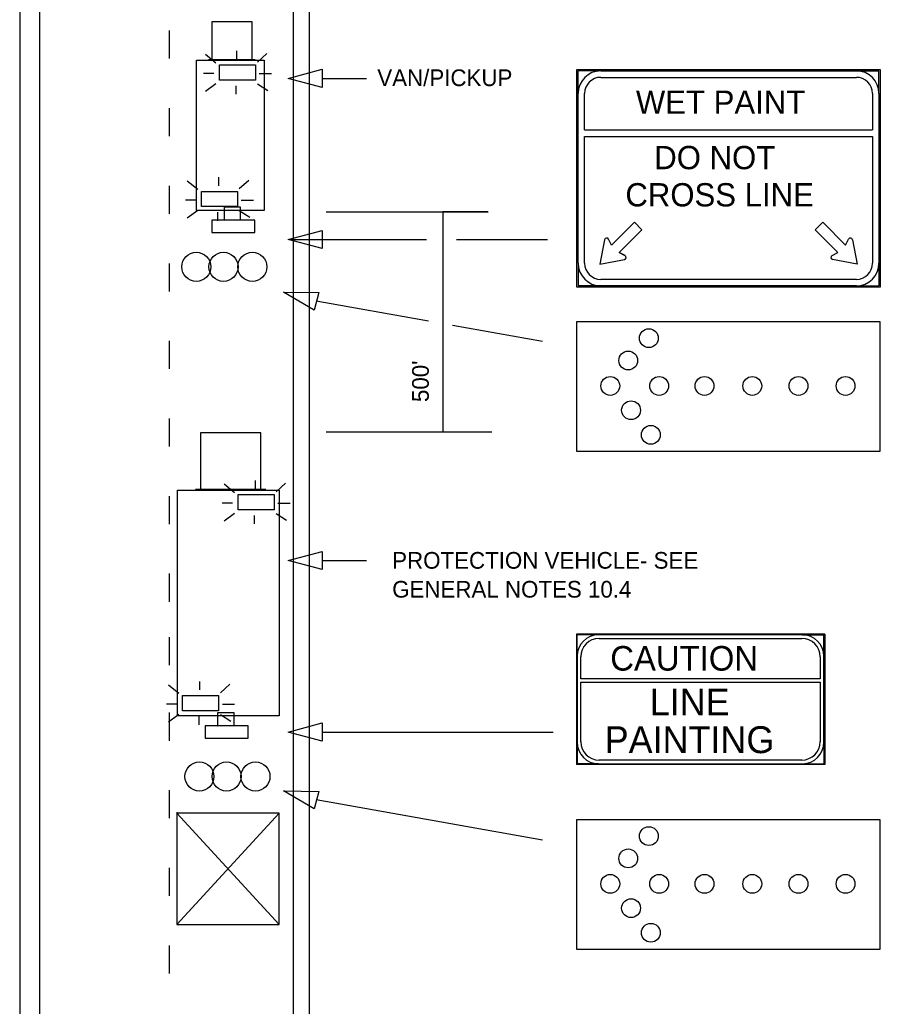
# Model space of a CAD drawing. Extents: x 1531.71 to 1538.58, y 1529.59 to 1539.48.
# Drawn here: x 1535.052 to 1538.149, y 1533.331 to 1536.879 of the extents above; entities that cross this region are included whole.
import ezdxf

# ---------------------------------------------------------------- set-up
doc = ezdxf.new("R2010")
doc.units = 0
for name, color, linetype in [('DETL-DIMS', 7, 'Continuous'), ('DETL-LINE', 7, 'Continuous'), ('DETL-NOTE', 7, 'Continuous'), ('USER-BORD', 7, 'Continuous')]:
    doc.layers.add(name, color=color, linetype=linetype)

# ---------------------------------------------------------------- blocks, each defined once
blk = doc.blocks.new('AP1')
at = {"layer": 'USER-BORD'}
for p, q in [((-0.0005, -0.0035), (-0.0005, -0.5033)), ((1.1745, -0.0035), (-0.0005, -0.0035)), ((0.1953, -0.0035), (0.1953, -0.0035)), ((0.3911, -0.0035), (0.3911, -0.0035)), ((0.587, -0.0035), (0.587, -0.0035)), ((0.7828, -0.0035), (0.7828, -0.0035)), ((0.9787, -0.0035), (0.9787, -0.0035)), ((1.1745, -0.5033), (1.1745, -0.0035)), ((-0.0005, -0.5033), (1.1745, -0.5033))]:
    blk.add_line(p, q, dxfattribs=at)
for centre in [(0.2793, -0.0665), (0.1995, -0.1528), (0.13, -0.2513), (0.3192, -0.2513), (0.4945, -0.2513), (0.6795, -0.2513), (0.858, -0.2513), (1.0402, -0.2513), (0.2103, -0.3452), (0.2869, -0.4403)]:
    blk.add_circle(centre, 0.0364, dxfattribs=at)
blk = doc.blocks.new('BAR')
at = {"layer": 'USER-BORD'}
for p, q in [((0.0695, 0.1172), (0.0695, 0.0842)), ((-0.011, 0.0696), (-0.0512, 0.1025)), ((0.15, 0.0732), (0.1866, 0.1062)), ((0.0037, 0.0037), (0.0037, 0.0622)), ((0.0037, 0.0622), (0.1427, 0.0622)), ((0.1427, 0.0622), (0.1427, 0.0037)), ((-0.0183, 0.0293), (-0.0585, 0.0293)), ((0.1427, 0.0037), (0.0037, 0.0037)), ((0.1573, 0.0293), (0.2049, 0.0293)), ((-0.011, -0.011), (-0.0512, -0.0403)), ((0.0658, -0.0183), (0.0658, -0.0513)), ((0.15, -0.011), (0.1902, -0.0366))]:
    blk.add_line(p, q, dxfattribs=at)
blk = doc.blocks.new('SIGN13')
at = {"layer": 'USER-BORD'}
for points in [[(-0.0134, 0.0182), (0.011, 0.0189), (0.011, 0.0371), (-0.0134, 0.0371)], [(-0.0314, 0.0182), (-0.0314, 0), (0.032, 0), (0.032, 0.0182)]]:
    blk.add_lwpolyline(points, close=True, dxfattribs=at)

msp = doc.modelspace()

# ---------------------------------------------------------------- linework, layer by layer
at = {"layer": 'DETL-DIMS'}
for p, q in [((1536.1408, 1536.6681), (1536.2998, 1536.6681)), ((1536.1554, 1536.1884), (1536.7372, 1536.1884)), ((1536.5747, 1536.1884), (1536.5747, 1535.3949)), ((1536.7372, 1536.1884), (1536.5747, 1536.1884)), ((1536.028, 1536.0882), (1536.3863, 1536.0882)), ((1536.3863, 1536.0882), (1536.5157, 1536.0882)), ((1536.6236, 1536.0882), (1536.951, 1536.0882)), ((1536.1184, 1535.8679), (1536.5226, 1535.796)), ((1536.6097, 1535.7805), (1536.933, 1535.723)), ((1536.7508, 1535.3949), (1536.1554, 1535.3949)), ((1536.1408, 1534.9341), (1536.2998, 1534.9341)), ((1536.1408, 1534.317), (1536.9717, 1534.317)), ((1536.1184, 1534.0741), (1536.933, 1533.9291))]:
    msp.add_line(p, q, dxfattribs=at)
for points in [[(1536.018, 1536.6681), (1536.1408, 1536.7007), (1536.1408, 1536.6356)], [(1536.018, 1536.0882), (1536.1408, 1536.1207), (1536.1408, 1536.0557)], [(1536.0018, 1535.899), (1536.1289, 1535.8975), (1536.1115, 1535.8347)], [(1536.018, 1534.9341), (1536.1408, 1534.9666), (1536.1408, 1534.9015)], [(1536.018, 1534.317), (1536.1408, 1534.3495), (1536.1408, 1534.2845)], [(1536.0018, 1534.105), (1536.1289, 1534.1035), (1536.1115, 1534.0407)]]:
    msp.add_lwpolyline(points, close=True, dxfattribs=at)
at = {"layer": 'DETL-LINE'}
for p, q in [((1535.0522, 1538.4412), (1535.0522, 1531.4327)), ((1535.1234, 1538.4412), (1535.1234, 1531.4327)), ((1536.0366, 1538.4412), (1536.0366, 1531.4327)), ((1536.0938, 1538.4412), (1536.0938, 1531.4327)), ((1535.8883, 1536.8711), (1535.743, 1536.8711)), ((1535.743, 1536.8711), (1535.743, 1536.7356)), ((1535.8883, 1536.7356), (1535.8883, 1536.8711)), ((1535.5917, 1536.7389), (1535.5917, 1536.8398)), ((1535.6879, 1536.1928), (1535.6879, 1536.7335)), ((1535.6879, 1536.7335), (1535.932, 1536.7335)), ((1535.7316, 1536.7356), (1535.8996, 1536.7356)), ((1535.761, 1536.7335), (1535.875, 1536.7335)), ((1535.932, 1536.7335), (1535.932, 1536.1928)), ((1537.0567, 1536.6997), (1538.1485, 1536.6997)), ((1537.0567, 1535.9169), (1537.0567, 1536.6997)), ((1537.1427, 1536.6949), (1537.0615, 1536.6949)), ((1537.0615, 1536.6137), (1537.0615, 1536.6949)), ((1537.1427, 1536.6949), (1538.0625, 1536.6949)), ((1538.0625, 1536.6949), (1538.1437, 1536.6949)), ((1538.1437, 1536.6137), (1538.1437, 1536.6949)), ((1538.1485, 1536.6997), (1538.1485, 1535.9169)), ((1537.1427, 1536.6717), (1538.0625, 1536.6717)), ((1537.0615, 1536.0029), (1537.0615, 1536.6137)), ((1537.0847, 1536.4824), (1537.0847, 1536.6137)), ((1538.1205, 1536.6137), (1538.1205, 1536.4824)), ((1538.1437, 1536.6137), (1538.1437, 1536.0029)), ((1535.5917, 1536.4599), (1535.5917, 1536.5608)), ((1537.0847, 1536.4824), (1538.1205, 1536.4824)), ((1537.0847, 1536.0029), (1537.0847, 1536.4592)), ((1537.0847, 1536.4592), (1538.1205, 1536.4592)), ((1538.1205, 1536.4592), (1538.1205, 1536.0029)), ((1535.5917, 1536.1809), (1535.5917, 1536.2817)), ((1535.932, 1536.1928), (1535.6879, 1536.1928)), ((1537.264, 1536.151), (1537.1815, 1536.0686)), ((1537.2092, 1536.0413), (1537.2912, 1536.1234)), ((1537.2912, 1536.1234), (1537.264, 1536.151)), ((1537.914, 1536.1234), (1537.9416, 1536.151)), ((1537.9964, 1536.0413), (1537.914, 1536.1234)), ((1537.9416, 1536.151), (1538.0236, 1536.0686)), ((1537.1567, 1536.0878), (1537.1399, 1535.9997)), ((1537.1815, 1536.0686), (1537.1707, 1536.0898)), ((1538.0236, 1536.0686), (1538.0344, 1536.0898)), ((1538.0485, 1536.0878), (1538.0653, 1535.9997)), ((1537.1399, 1535.9997), (1537.228, 1536.0165)), ((1537.2092, 1536.0413), (1537.23, 1536.0305)), ((1537.2301, 1536.0306), (1537.2092, 1536.0413)), ((1537.9752, 1536.0305), (1537.9964, 1536.0413)), ((1538.0653, 1535.9997), (1537.9772, 1536.0165)), ((1535.5917, 1535.9018), (1535.5917, 1536.0027)), ((1537.0615, 1536.0029), (1537.0615, 1535.9217)), ((1538.1437, 1536.0029), (1538.1437, 1535.9217)), ((1538.0625, 1535.9449), (1537.1427, 1535.9449)), ((1538.1485, 1535.9169), (1537.0567, 1535.9169)), ((1537.1427, 1535.9217), (1537.0615, 1535.9217)), ((1538.0625, 1535.9217), (1537.1427, 1535.9217)), ((1538.0625, 1535.9217), (1538.1437, 1535.9217)), ((1535.5917, 1535.6228), (1535.5917, 1535.7237)), ((1535.5917, 1535.3438), (1535.5917, 1535.4447)), ((1535.9203, 1535.3934), (1535.7022, 1535.3934)), ((1535.7022, 1535.3934), (1535.7022, 1535.1901)), ((1535.9203, 1535.1901), (1535.9203, 1535.3934)), ((1535.5917, 1535.0648), (1535.5917, 1535.1657)), ((1535.6194, 1534.3749), (1535.6194, 1535.1868)), ((1535.6194, 1535.1868), (1535.986, 1535.1868)), ((1535.6851, 1535.1901), (1535.9374, 1535.1901)), ((1535.7293, 1535.1868), (1535.9003, 1535.1868)), ((1535.986, 1535.1868), (1535.986, 1534.3749)), ((1535.5917, 1534.7857), (1535.5917, 1534.8867)), ((1537.055, 1534.6693), (1537.055, 1534.2001)), ((1537.9485, 1534.6693), (1537.055, 1534.6693)), ((1537.1348, 1534.6667), (1537.0576, 1534.6667)), ((1537.0576, 1534.5893), (1537.0576, 1534.6667)), ((1537.8684, 1534.6667), (1537.1348, 1534.6667)), ((1537.8684, 1534.6667), (1537.9455, 1534.6667)), ((1537.9455, 1534.5893), (1537.9455, 1534.6667)), ((1537.9485, 1534.6693), (1537.9485, 1534.2001)), ((1535.5917, 1534.5579), (1535.5917, 1534.6587)), ((1537.1371, 1534.6535), (1537.8661, 1534.6535)), ((1537.0576, 1534.5893), (1537.0576, 1534.2802)), ((1537.0709, 1534.5079), (1537.0709, 1534.5869)), ((1537.9323, 1534.5869), (1537.9323, 1534.5079)), ((1537.9455, 1534.5893), (1537.9455, 1534.2802)), ((1537.9455, 1534.2802), (1537.9455, 1534.5893)), ((1537.9323, 1534.5079), (1537.0709, 1534.5079)), ((1537.0709, 1534.4959), (1537.9323, 1534.4959)), ((1537.0709, 1534.2821), (1537.0709, 1534.4959)), ((1537.9323, 1534.4959), (1537.9323, 1534.2821)), ((1535.5917, 1534.2857), (1535.5917, 1534.3866)), ((1535.986, 1534.3749), (1535.6194, 1534.3749)), ((1537.0576, 1534.2802), (1537.0576, 1534.2027)), ((1537.9455, 1534.2802), (1537.9455, 1534.2027)), ((1537.9485, 1534.2001), (1537.055, 1534.2001)), ((1537.1348, 1534.2027), (1537.0576, 1534.2027)), ((1537.1348, 1534.2027), (1537.8684, 1534.2027)), ((1537.8661, 1534.216), (1537.1371, 1534.216)), ((1537.8684, 1534.2027), (1537.9455, 1534.2027)), ((1535.5917, 1534.0066), (1535.5917, 1534.1075)), ((1535.6178, 1534.0288), (1535.6178, 1533.6241)), ((1535.9852, 1534.0255), (1535.6178, 1534.0255)), ((1535.9852, 1534.0255), (1535.6178, 1533.6241)), ((1535.6178, 1534.0255), (1535.9852, 1533.6241)), ((1535.9852, 1533.6241), (1535.9852, 1534.0255)), ((1535.5917, 1533.7276), (1535.5917, 1533.8285)), ((1535.6178, 1533.6241), (1535.9852, 1533.6241)), ((1535.5917, 1533.4486), (1535.5917, 1533.5495))]:
    msp.add_line(p, q, dxfattribs=at)
for centre in [(1535.6876, 1535.9902), (1535.7854, 1535.9902), (1535.8893, 1535.9902), (1535.6987, 1534.1569), (1535.7965, 1534.1569), (1535.9003, 1534.1569)]:
    msp.add_circle(centre, 0.0523, dxfattribs=at)
for centre, radius, start, end in [((1537.1427, 1536.6137), 0.0812, 90, 180), ((1538.0626, 1536.6137), 0.0812, 0, 90), ((1537.1427, 1536.6137), 0.058, 90, 180), ((1538.0626, 1536.6137), 0.058, 0, 90), ((1537.1642, 1536.0863), 0.00759, 27, 169.2603), ((1538.0412, 1536.0863), 0.00759, 10.7397, 153), ((1537.2266, 1536.0239), 0.00759, 280.7397, 63), ((1537.9787, 1536.0239), 0.00759, 117, 259.2603), ((1537.1427, 1536.0031), 0.0812, 180, 270), ((1537.1427, 1536.003), 0.058, 180, 270), ((1538.0626, 1536.0031), 0.0812, 270, 0), ((1538.0626, 1536.003), 0.058, 270, 0), ((1537.1349, 1534.5893), 0.0773, 90, 180), ((1537.8684, 1534.5893), 0.0773, 0, 90), ((1537.1371, 1534.5871), 0.0663, 90, 180), ((1537.8661, 1534.5871), 0.0663, 0, 90), ((1537.1349, 1534.2801), 0.0773, 180, 270), ((1537.1371, 1534.2823), 0.0663, 180, 270), ((1537.8661, 1534.2823), 0.0663, 270, 0), ((1537.8684, 1534.2801), 0.0773, 270, 0)]:
    msp.add_arc(centre, radius, start, end, dxfattribs=at)

# ---------------------------------------------------------------- block references
for name, p, xscale, yscale in [('BAR', (1535.768, 1536.6583), 0.930070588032, 0.930070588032), ('BAR', (1535.7027, 1536.2032), 0.930070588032, 0.930070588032), ('SIGN13', (1535.8202, 1536.1135), 2.4478231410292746, 2.4478231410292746), ('AP1', (1537.0562, 1535.7954), 0.930070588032, 0.930070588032), ('BAR', (1535.835, 1535.1129), 0.930070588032, 0.930070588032), ('BAR', (1535.635, 1534.3902), 0.930070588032, 0.930070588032), ('SIGN13', (1535.7963, 1534.2951), 2.4478231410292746, 2.4478231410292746), ('AP1', (1537.0562, 1534.0045), 0.930070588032, 0.930070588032)]:
    msp.add_blockref(name, p, dxfattribs=dict(at, xscale=xscale, yscale=yscale))

# ---------------------------------------------------------------- texts
for s, p in [('WET PAINT', (1537.2693, 1536.5405)), ('DO NOT', (1537.3354, 1536.3413)), ('CROSS LINE', (1537.2315, 1536.2074))]:
    msp.add_text(s, height=0.0837, dxfattribs=at).set_placement(p)
for s, height, p in [('CAUTION', 0.08839, (1537.177, 1534.5378)), ('LINE', 0.09664, (1537.3193, 1534.3765)), ('PAINTING', 0.09664, (1537.1569, 1534.2409))]:
    msp.add_text(s, height=height, rotation=0.0085, dxfattribs=at).set_placement(p)
at = {"layer": 'DETL-NOTE'}
for s, p in [('VAN/PICKUP', (1536.3389, 1536.6402)), ('PROTECTION VEHICLE- SEE', (1536.3924, 1534.9044)), ('GENERAL NOTES 10.4', (1536.3924, 1534.8004))]:
    msp.add_text(s, height=0.06, dxfattribs=at).set_placement(p)
msp.add_text("500'", height=0.06, rotation=90, dxfattribs=at).set_placement((1536.5241, 1535.5038))

doc.saveas('drawing.dxf')
